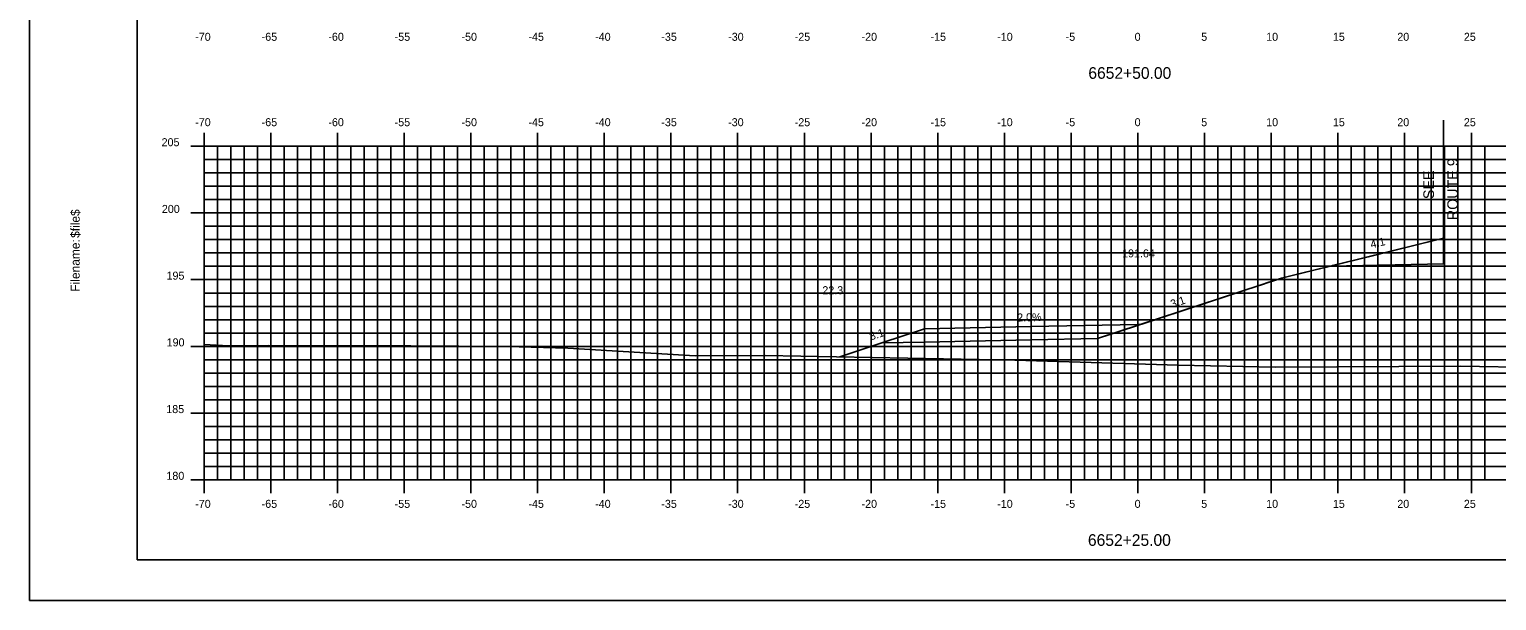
# Model space of a CAD drawing. Extents: x 1723986 to 1724158, y 458501 to 458611.
# Drawn here: x 1723986.2 to 1724096.2, y 458501.2 to 458544 of the extents above; entities that cross this region are included whole.
import ezdxf

# ---------------------------------------------------------------- set-up
doc = ezdxf.new("R2010")
doc.units = 0
for name, color, linetype in [('ANNOTATION', 7, 'Continuous'), ('BORDER', 7, 'Continuous'), ('D_Roadway_Centerline', 7, 'Continuous'), ('D_Roadway_Centerline_Text', 7, 'Continuous'), ('D_Roadway_Drive_Gravel', 7, 'Continuous'), ('D_Roadway_Edge_Shoulder', 7, 'Continuous'), ('D_Roadway_SlopeLines', 7, 'Continuous'), ('D_Roadway_SubGrade', 7, 'Continuous'), ('D_Text_Standard', 7, 'Continuous'), ('H_V ANNOTATION', 7, 'Continuous'), ('MAJOR', 7, 'Continuous'), ('MINOR', 7, 'Continuous'), ('PLOT BOUNDARY', 7, 'Continuous'), ('S_Roadway_Centerline', 7, 'Continuous')]:
    doc.layers.add(name, color=color, linetype=linetype)

msp = doc.modelspace()

# ---------------------------------------------------------------- linework, layer by layer
at = {"layer": 'BORDER'}
msp.add_lwpolyline([(1723994.3, 458504.25), (1724154.3, 458504.25), (1724154.3, 458609.25), (1723994.3, 458609.25)], close=True, dxfattribs=at)
at = {"layer": 'D_Roadway_Centerline'}
msp.add_lwpolyline([(1724066.27, 458520.83), (1724070.89, 458522.35), (1724070.99, 458522.38), (1724071.09, 458522.42), (1724076.05, 458524.05), (1724077.39, 458524.48), (1724078.79, 458524.94), (1724078.89, 458524.98), (1724080.06, 458525.36), (1724081.68, 458525.76), (1724083.74, 458526.27), (1724083.84, 458526.29), (1724083.89, 458526.31), (1724085.95, 458526.81), (1724086.68, 458526.99), (1724088.37, 458527.41), (1724090.39, 458527.91), (1724090.98, 458528.05), (1724092.21, 458528.35)], dxfattribs=at)
at = {"layer": 'D_Roadway_Drive_Gravel'}
msp.add_lwpolyline([(1724069.3, 458521.89), (1724061.3, 458521.73), (1724053.3, 458521.57), (1724050.11, 458520.51), (1724053.3, 458520.57), (1724061.3, 458520.73), (1724066.27, 458520.83)], dxfattribs=at)
at = {"layer": 'D_Roadway_Edge_Shoulder'}
msp.add_line((1724092.21, 458528.35), (1724092.21, 458528.1), dxfattribs=at)
msp.add_line((1724092.21, 458528.35), (1724092.21, 458528.1), dxfattribs=at)
at = {"layer": 'D_Roadway_SlopeLines'}
for points in [[(1724092.21, 458528.35), (1724080.06, 458525.36), (1724066.27, 458520.83)], [(1724092.21, 458528.35), (1724080.06, 458525.36), (1724066.27, 458520.83)], [(1724092.21, 458528.35), (1724080.06, 458525.36), (1724066.27, 458520.83)], [(1724092.21, 458528.35), (1724080.06, 458525.36), (1724066.27, 458520.83)], [(1724092.21, 458528.35), (1724080.06, 458525.36), (1724066.27, 458520.83)], [(1724092.21, 458528.35), (1724080.06, 458525.36), (1724066.27, 458520.83)], [(1724092.21, 458528.35), (1724080.06, 458525.36)], [(1724092.21, 458528.35), (1724080.06, 458525.36)], [(1724092.21, 458528.35), (1724083.74, 458526.27)], [(1724053.3, 458521.57), (1724050.11, 458520.51), (1724046.95, 458519.46)], [(1724069.3, 458521.89), (1724069.51, 458521.9)]]:
    msp.add_lwpolyline(points, dxfattribs=at)
at = {"layer": 'D_Roadway_SubGrade'}
msp.add_line((1724092.21, 458537.21), (1724092.21, 458526.43), dxfattribs=at)
for points in [[(1724092.21, 458526.43), (1724083.74, 458526.27), (1724092.21, 458528.35), (1724092.21, 458528.1)], [(1724092.21, 458528.1), (1724092.21, 458528.35), (1724083.74, 458526.27), (1724092.21, 458526.43)]]:
    msp.add_lwpolyline(points, dxfattribs=at)
at = {"layer": 'MAJOR'}
for p, q in [((1723999.3, 458536.26), (1723999.3, 458535.25)), ((1724004.3, 458536.26), (1724004.3, 458535.25)), ((1724009.3, 458536.26), (1724009.3, 458535.25)), ((1724014.3, 458536.26), (1724014.3, 458535.25)), ((1724019.3, 458536.26), (1724019.3, 458535.25)), ((1724024.3, 458536.26), (1724024.3, 458535.25)), ((1724029.3, 458536.26), (1724029.3, 458535.25)), ((1724034.3, 458536.26), (1724034.3, 458535.25)), ((1724039.3, 458536.26), (1724039.3, 458535.25)), ((1724044.3, 458536.26), (1724044.3, 458535.25)), ((1724049.3, 458536.26), (1724049.3, 458535.25)), ((1724054.3, 458536.26), (1724054.3, 458535.25)), ((1724059.3, 458536.26), (1724059.3, 458535.25)), ((1724064.3, 458536.26), (1724064.3, 458535.25)), ((1724069.3, 458536.26), (1724069.3, 458535.25)), ((1724074.3, 458536.26), (1724074.3, 458535.25)), ((1724079.3, 458536.26), (1724079.3, 458535.25)), ((1724084.3, 458536.26), (1724084.3, 458535.25)), ((1724089.3, 458536.26), (1724089.3, 458535.25)), ((1724094.3, 458536.26), (1724094.3, 458535.25)), ((1723998.3, 458535.25), (1723999.3, 458535.25)), ((1723999.3, 458535.25), (1724139.3, 458535.25)), ((1723999.3, 458510.25), (1723999.3, 458535.25)), ((1723999.3, 458510.25), (1723999.3, 458535.25)), ((1723999.3, 458535.25), (1724139.3, 458535.25)), ((1724004.3, 458510.25), (1724004.3, 458535.25)), ((1724009.3, 458510.25), (1724009.3, 458535.25)), ((1724014.3, 458510.25), (1724014.3, 458535.25)), ((1724019.3, 458510.25), (1724019.3, 458535.25)), ((1724024.3, 458510.25), (1724024.3, 458535.25)), ((1724029.3, 458510.25), (1724029.3, 458535.25)), ((1724034.3, 458510.25), (1724034.3, 458535.25)), ((1724039.3, 458510.25), (1724039.3, 458535.25)), ((1724044.3, 458510.25), (1724044.3, 458535.25)), ((1724049.3, 458510.25), (1724049.3, 458535.25)), ((1724054.3, 458510.25), (1724054.3, 458535.25)), ((1724059.3, 458510.25), (1724059.3, 458535.25)), ((1724064.3, 458510.25), (1724064.3, 458535.25)), ((1724069.3, 458510.25), (1724069.3, 458535.25)), ((1724074.3, 458510.25), (1724074.3, 458535.25)), ((1724079.3, 458510.25), (1724079.3, 458535.25)), ((1724084.3, 458510.25), (1724084.3, 458535.25)), ((1724089.3, 458510.25), (1724089.3, 458535.25)), ((1724094.3, 458510.25), (1724094.3, 458535.25)), ((1723998.3, 458530.25), (1723999.3, 458530.25)), ((1723999.3, 458530.25), (1724139.3, 458530.25)), ((1723998.3, 458525.25), (1723999.3, 458525.25)), ((1723999.3, 458525.25), (1724139.3, 458525.25)), ((1723998.3, 458520.25), (1723999.3, 458520.25)), ((1723999.3, 458520.25), (1724139.3, 458520.25)), ((1723998.3, 458515.25), (1723999.3, 458515.25)), ((1723999.3, 458515.25), (1724139.3, 458515.25)), ((1723998.3, 458510.25), (1723999.3, 458510.25)), ((1723999.3, 458510.25), (1724139.3, 458510.25)), ((1723999.3, 458510.25), (1724139.3, 458510.25)), ((1723999.3, 458509.25), (1723999.3, 458510.25)), ((1724004.3, 458509.25), (1724004.3, 458510.25)), ((1724009.3, 458509.25), (1724009.3, 458510.25)), ((1724014.3, 458509.25), (1724014.3, 458510.25)), ((1724019.3, 458509.25), (1724019.3, 458510.25)), ((1724024.3, 458509.25), (1724024.3, 458510.25)), ((1724029.3, 458509.25), (1724029.3, 458510.25)), ((1724034.3, 458509.25), (1724034.3, 458510.25)), ((1724039.3, 458509.25), (1724039.3, 458510.25)), ((1724044.3, 458509.25), (1724044.3, 458510.25)), ((1724049.3, 458509.25), (1724049.3, 458510.25)), ((1724054.3, 458509.25), (1724054.3, 458510.25)), ((1724059.3, 458509.25), (1724059.3, 458510.25)), ((1724064.3, 458509.25), (1724064.3, 458510.25)), ((1724069.3, 458509.25), (1724069.3, 458510.25)), ((1724074.3, 458509.25), (1724074.3, 458510.25)), ((1724079.3, 458509.25), (1724079.3, 458510.25)), ((1724084.3, 458509.25), (1724084.3, 458510.25)), ((1724089.3, 458509.25), (1724089.3, 458510.25)), ((1724094.3, 458509.25), (1724094.3, 458510.25))]:
    msp.add_line(p, q, dxfattribs=at)
at = {"layer": 'MINOR'}
for p, q in [((1724000.3, 458510.25), (1724000.3, 458535.25)), ((1724001.3, 458510.25), (1724001.3, 458535.25)), ((1724002.3, 458510.25), (1724002.3, 458535.25)), ((1724003.3, 458510.25), (1724003.3, 458535.25)), ((1724005.3, 458510.25), (1724005.3, 458535.25)), ((1724006.3, 458510.25), (1724006.3, 458535.25)), ((1724007.3, 458510.25), (1724007.3, 458535.25)), ((1724008.3, 458510.25), (1724008.3, 458535.25)), ((1724010.3, 458510.25), (1724010.3, 458535.25)), ((1724011.3, 458510.25), (1724011.3, 458535.25)), ((1724012.3, 458510.25), (1724012.3, 458535.25)), ((1724013.3, 458510.25), (1724013.3, 458535.25)), ((1724015.3, 458510.25), (1724015.3, 458535.25)), ((1724016.3, 458510.25), (1724016.3, 458535.25)), ((1724017.3, 458510.25), (1724017.3, 458535.25)), ((1724018.3, 458510.25), (1724018.3, 458535.25)), ((1724020.3, 458510.25), (1724020.3, 458535.25)), ((1724021.3, 458510.25), (1724021.3, 458535.25)), ((1724022.3, 458510.25), (1724022.3, 458535.25)), ((1724023.3, 458510.25), (1724023.3, 458535.25)), ((1724025.3, 458510.25), (1724025.3, 458535.25)), ((1724026.3, 458510.25), (1724026.3, 458535.25)), ((1724027.3, 458510.25), (1724027.3, 458535.25)), ((1724028.3, 458510.25), (1724028.3, 458535.25)), ((1724030.3, 458510.25), (1724030.3, 458535.25)), ((1724031.3, 458510.25), (1724031.3, 458535.25)), ((1724032.3, 458510.25), (1724032.3, 458535.25)), ((1724033.3, 458510.25), (1724033.3, 458535.25)), ((1724035.3, 458510.25), (1724035.3, 458535.25)), ((1724036.3, 458510.25), (1724036.3, 458535.25)), ((1724037.3, 458510.25), (1724037.3, 458535.25)), ((1724038.3, 458510.25), (1724038.3, 458535.25)), ((1724040.3, 458510.25), (1724040.3, 458535.25)), ((1724041.3, 458510.25), (1724041.3, 458535.25)), ((1724042.3, 458510.25), (1724042.3, 458535.25)), ((1724043.3, 458510.25), (1724043.3, 458535.25)), ((1724045.3, 458510.25), (1724045.3, 458535.25)), ((1724046.3, 458510.25), (1724046.3, 458535.25)), ((1724047.3, 458510.25), (1724047.3, 458535.25)), ((1724048.3, 458510.25), (1724048.3, 458535.25)), ((1724050.3, 458510.25), (1724050.3, 458535.25)), ((1724051.3, 458510.25), (1724051.3, 458535.25)), ((1724052.3, 458510.25), (1724052.3, 458535.25)), ((1724053.3, 458510.25), (1724053.3, 458535.25)), ((1724055.3, 458510.25), (1724055.3, 458535.25)), ((1724056.3, 458510.25), (1724056.3, 458535.25)), ((1724057.3, 458510.25), (1724057.3, 458535.25)), ((1724058.3, 458510.25), (1724058.3, 458535.25)), ((1724060.3, 458510.25), (1724060.3, 458535.25)), ((1724061.3, 458510.25), (1724061.3, 458535.25)), ((1724062.3, 458510.25), (1724062.3, 458535.25)), ((1724063.3, 458510.25), (1724063.3, 458535.25)), ((1724065.3, 458510.25), (1724065.3, 458535.25)), ((1724066.3, 458510.25), (1724066.3, 458535.25)), ((1724067.3, 458510.25), (1724067.3, 458535.25)), ((1724068.3, 458510.25), (1724068.3, 458535.25)), ((1724070.3, 458510.25), (1724070.3, 458535.25)), ((1724071.3, 458510.25), (1724071.3, 458535.25)), ((1724072.3, 458510.25), (1724072.3, 458535.25)), ((1724073.3, 458510.25), (1724073.3, 458535.25)), ((1724075.3, 458510.25), (1724075.3, 458535.25)), ((1724076.3, 458510.25), (1724076.3, 458535.25)), ((1724077.3, 458510.25), (1724077.3, 458535.25)), ((1724078.3, 458510.25), (1724078.3, 458535.25)), ((1724080.3, 458510.25), (1724080.3, 458535.25)), ((1724081.3, 458510.25), (1724081.3, 458535.25)), ((1724082.3, 458510.25), (1724082.3, 458535.25)), ((1724083.3, 458510.25), (1724083.3, 458535.25)), ((1724085.3, 458510.25), (1724085.3, 458535.25)), ((1724086.3, 458510.25), (1724086.3, 458535.25)), ((1724087.3, 458510.25), (1724087.3, 458535.25)), ((1724088.3, 458510.25), (1724088.3, 458535.25)), ((1724090.3, 458510.25), (1724090.3, 458535.25)), ((1724091.3, 458510.25), (1724091.3, 458535.25)), ((1724092.3, 458510.25), (1724092.3, 458535.25)), ((1724093.3, 458510.25), (1724093.3, 458535.25)), ((1724095.3, 458510.25), (1724095.3, 458535.25)), ((1723999.3, 458534.25), (1724139.3, 458534.25)), ((1723999.3, 458534.25), (1724000.3, 458534.25)), ((1723999.3, 458533.25), (1724139.3, 458533.25)), ((1723999.3, 458533.25), (1724000.3, 458533.25)), ((1723999.3, 458532.25), (1724139.3, 458532.25)), ((1723999.3, 458532.25), (1724000.3, 458532.25)), ((1723999.3, 458531.25), (1724139.3, 458531.25)), ((1723999.3, 458531.25), (1724000.3, 458531.25)), ((1723999.3, 458529.25), (1724139.3, 458529.25)), ((1723999.3, 458529.25), (1724000.3, 458529.25)), ((1723999.3, 458528.25), (1724139.3, 458528.25)), ((1723999.3, 458528.25), (1724000.3, 458528.25)), ((1723999.3, 458527.25), (1724139.3, 458527.25)), ((1723999.3, 458527.25), (1724000.3, 458527.25)), ((1723999.3, 458526.25), (1724139.3, 458526.25)), ((1723999.3, 458526.25), (1724000.3, 458526.25)), ((1723999.3, 458524.25), (1724139.3, 458524.25)), ((1723999.3, 458524.25), (1724000.3, 458524.25)), ((1723999.3, 458523.25), (1724139.3, 458523.25)), ((1723999.3, 458523.25), (1724000.3, 458523.25)), ((1723999.3, 458522.25), (1724139.3, 458522.25)), ((1723999.3, 458522.25), (1724000.3, 458522.25)), ((1723999.3, 458521.25), (1724139.3, 458521.25)), ((1723999.3, 458521.25), (1724000.3, 458521.25)), ((1723999.3, 458519.25), (1724139.3, 458519.25)), ((1723999.3, 458519.25), (1724000.3, 458519.25)), ((1723999.3, 458518.25), (1724139.3, 458518.25)), ((1723999.3, 458518.25), (1724000.3, 458518.25)), ((1723999.3, 458517.25), (1724139.3, 458517.25)), ((1723999.3, 458517.25), (1724000.3, 458517.25)), ((1723999.3, 458516.25), (1724139.3, 458516.25)), ((1723999.3, 458516.25), (1724000.3, 458516.25)), ((1723999.3, 458514.25), (1724139.3, 458514.25)), ((1723999.3, 458514.25), (1724000.3, 458514.25)), ((1723999.3, 458513.25), (1724139.3, 458513.25)), ((1723999.3, 458513.25), (1724000.3, 458513.25)), ((1723999.3, 458512.25), (1724139.3, 458512.25)), ((1723999.3, 458512.25), (1724000.3, 458512.25)), ((1723999.3, 458511.25), (1724139.3, 458511.25)), ((1723999.3, 458511.25), (1724000.3, 458511.25))]:
    msp.add_line(p, q, dxfattribs=at)
at = {"layer": 'PLOT BOUNDARY'}
msp.add_lwpolyline([(1723986.21, 458501.2), (1724156.21, 458501.2), (1724156.21, 458611.2), (1723986.21, 458611.2)], close=True, dxfattribs=at)
at = {"layer": 'S_Roadway_Centerline'}
msp.add_lwpolyline([(1723999.3, 458520.4), (1724001.14, 458520.3), (1724004.1, 458520.32), (1724014.81, 458520.28), (1724021.99, 458520.23), (1724026.56, 458520.11), (1724036.11, 458519.54), (1724041.36, 458519.56), (1724060.09, 458519.21), (1724072.33, 458518.85), (1724079.59, 458518.68), (1724093.49, 458518.76), (1724099.17, 458518.67), (1724107.74, 458518.16), (1724118.11, 458517.41), (1724120.7, 458517.29), (1724125.08, 458517.24), (1724137.3, 458517.19), (1724139.3, 458517.07)], dxfattribs=at)

# ---------------------------------------------------------------- texts
at = {"layer": 'ANNOTATION'}
for s, height, rotation, p in [('ROUTE 9', 0.8, 90, (1724093.3, 458529.71)), ('SEE', 0.8, 90, (1724091.5, 458531.29)), ('4:1', 0.6, 13.6162, (1724086.81, 458527.59)), ('3:1', 0.6, 18.4349, (1724071.86, 458523.12)), ('2.0%', 0.6, 1.1458, (1724060.26, 458522.11)), ('3:1', 0.6, 18.4349, (1724049.29, 458520.69))]:
    msp.add_text(s, height=height, rotation=rotation, dxfattribs=at).set_placement(p)
at = {"layer": 'BORDER'}
for s, p in [('$file$', (1723989.98, 458528.38)), ('Filename:', (1723989.98, 458524.35))]:
    msp.add_text(s, height=0.67, rotation=90, dxfattribs=at).set_placement(p)
at = {"layer": 'D_Roadway_Centerline_Text'}
msp.add_text('191.64', height=0.6, dxfattribs=at).set_placement((1724068.12, 458526.92))
at = {"layer": 'D_Text_Standard'}
msp.add_text("22.3'", height=0.6, dxfattribs=at).set_placement((1724045.65, 458524.16))
at = {"layer": 'H_V ANNOTATION'}
for s, height, p in [('-70', 0.6, (1723998.64, 458543.15)), ('-65', 0.6, (1724003.62, 458543.15)), ('-60', 0.6, (1724008.62, 458543.15)), ('-55', 0.6, (1724013.59, 458543.15)), ('-50', 0.6, (1724018.6, 458543.15)), ('-45', 0.6, (1724023.62, 458543.15)), ('-40', 0.6, (1724028.62, 458543.15)), ('-35', 0.6, (1724033.58, 458543.15)), ('-30', 0.6, (1724038.59, 458543.15)), ('-25', 0.6, (1724043.58, 458543.15)), ('-20', 0.6, (1724048.59, 458543.15)), ('-15', 0.6, (1724053.76, 458543.15)), ('-10', 0.6, (1724058.76, 458543.15)), ('-5', 0.6, (1724063.89, 458543.15)), ('0', 0.6, (1724069.06, 458543.15)), ('5', 0.6, (1724074.05, 458543.15)), ('10', 0.6, (1724078.92, 458543.15)), ('15', 0.6, (1724083.92, 458543.15)), ('20', 0.6, (1724088.75, 458543.15)), ('25', 0.6, (1724093.74, 458543.15)), ('6652+50.00', 0.875, (1724065.59, 458540.3)), ('-70', 0.6, (1723998.64, 458536.75)), ('-65', 0.6, (1724003.62, 458536.75)), ('-60', 0.6, (1724008.62, 458536.75)), ('-55', 0.6, (1724013.59, 458536.75)), ('-50', 0.6, (1724018.6, 458536.75)), ('-45', 0.6, (1724023.62, 458536.75)), ('-40', 0.6, (1724028.62, 458536.75)), ('-35', 0.6, (1724033.58, 458536.75)), ('-30', 0.6, (1724038.59, 458536.75)), ('-25', 0.6, (1724043.58, 458536.75)), ('-20', 0.6, (1724048.59, 458536.75)), ('-15', 0.6, (1724053.76, 458536.75)), ('-10', 0.6, (1724058.76, 458536.75)), ('-5', 0.6, (1724063.89, 458536.75)), ('0', 0.6, (1724069.06, 458536.75)), ('5', 0.6, (1724074.05, 458536.75)), ('10', 0.6, (1724078.92, 458536.75)), ('15', 0.6, (1724083.92, 458536.75)), ('20', 0.6, (1724088.75, 458536.75)), ('25', 0.6, (1724093.74, 458536.75)), ('205', 0.6, (1723996.12, 458535.25)), ('200', 0.6, (1723996.14, 458530.25)), ('195', 0.6, (1723996.49, 458525.25)), ('190', 0.6, (1723996.5, 458520.25)), ('185', 0.6, (1723996.47, 458515.25)), ('180', 0.6, (1723996.48, 458510.25)), ('-70', 0.6, (1723998.64, 458508.15)), ('-65', 0.6, (1724003.62, 458508.15)), ('-60', 0.6, (1724008.62, 458508.15)), ('-55', 0.6, (1724013.59, 458508.15)), ('-50', 0.6, (1724018.6, 458508.15)), ('-45', 0.6, (1724023.62, 458508.15)), ('-40', 0.6, (1724028.62, 458508.15)), ('-35', 0.6, (1724033.58, 458508.15)), ('-30', 0.6, (1724038.59, 458508.15)), ('-25', 0.6, (1724043.58, 458508.15)), ('-20', 0.6, (1724048.59, 458508.15)), ('-15', 0.6, (1724053.76, 458508.15)), ('-10', 0.6, (1724058.76, 458508.15)), ('-5', 0.6, (1724063.89, 458508.15)), ('0', 0.6, (1724069.06, 458508.15)), ('5', 0.6, (1724074.05, 458508.15)), ('10', 0.6, (1724078.92, 458508.15)), ('15', 0.6, (1724083.92, 458508.15)), ('20', 0.6, (1724088.75, 458508.15)), ('25', 0.6, (1724093.74, 458508.15)), ('6652+25.00', 0.875, (1724065.56, 458505.3))]:
    msp.add_text(s, height=height, dxfattribs=at).set_placement(p)
at = {"layer": 'MAJOR'}
msp.add_text('-', height=0.006, dxfattribs=at).set_placement((1723999.29, 458510.25))

doc.saveas('drawing.dxf')
